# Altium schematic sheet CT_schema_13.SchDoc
size 385 x 385 mm
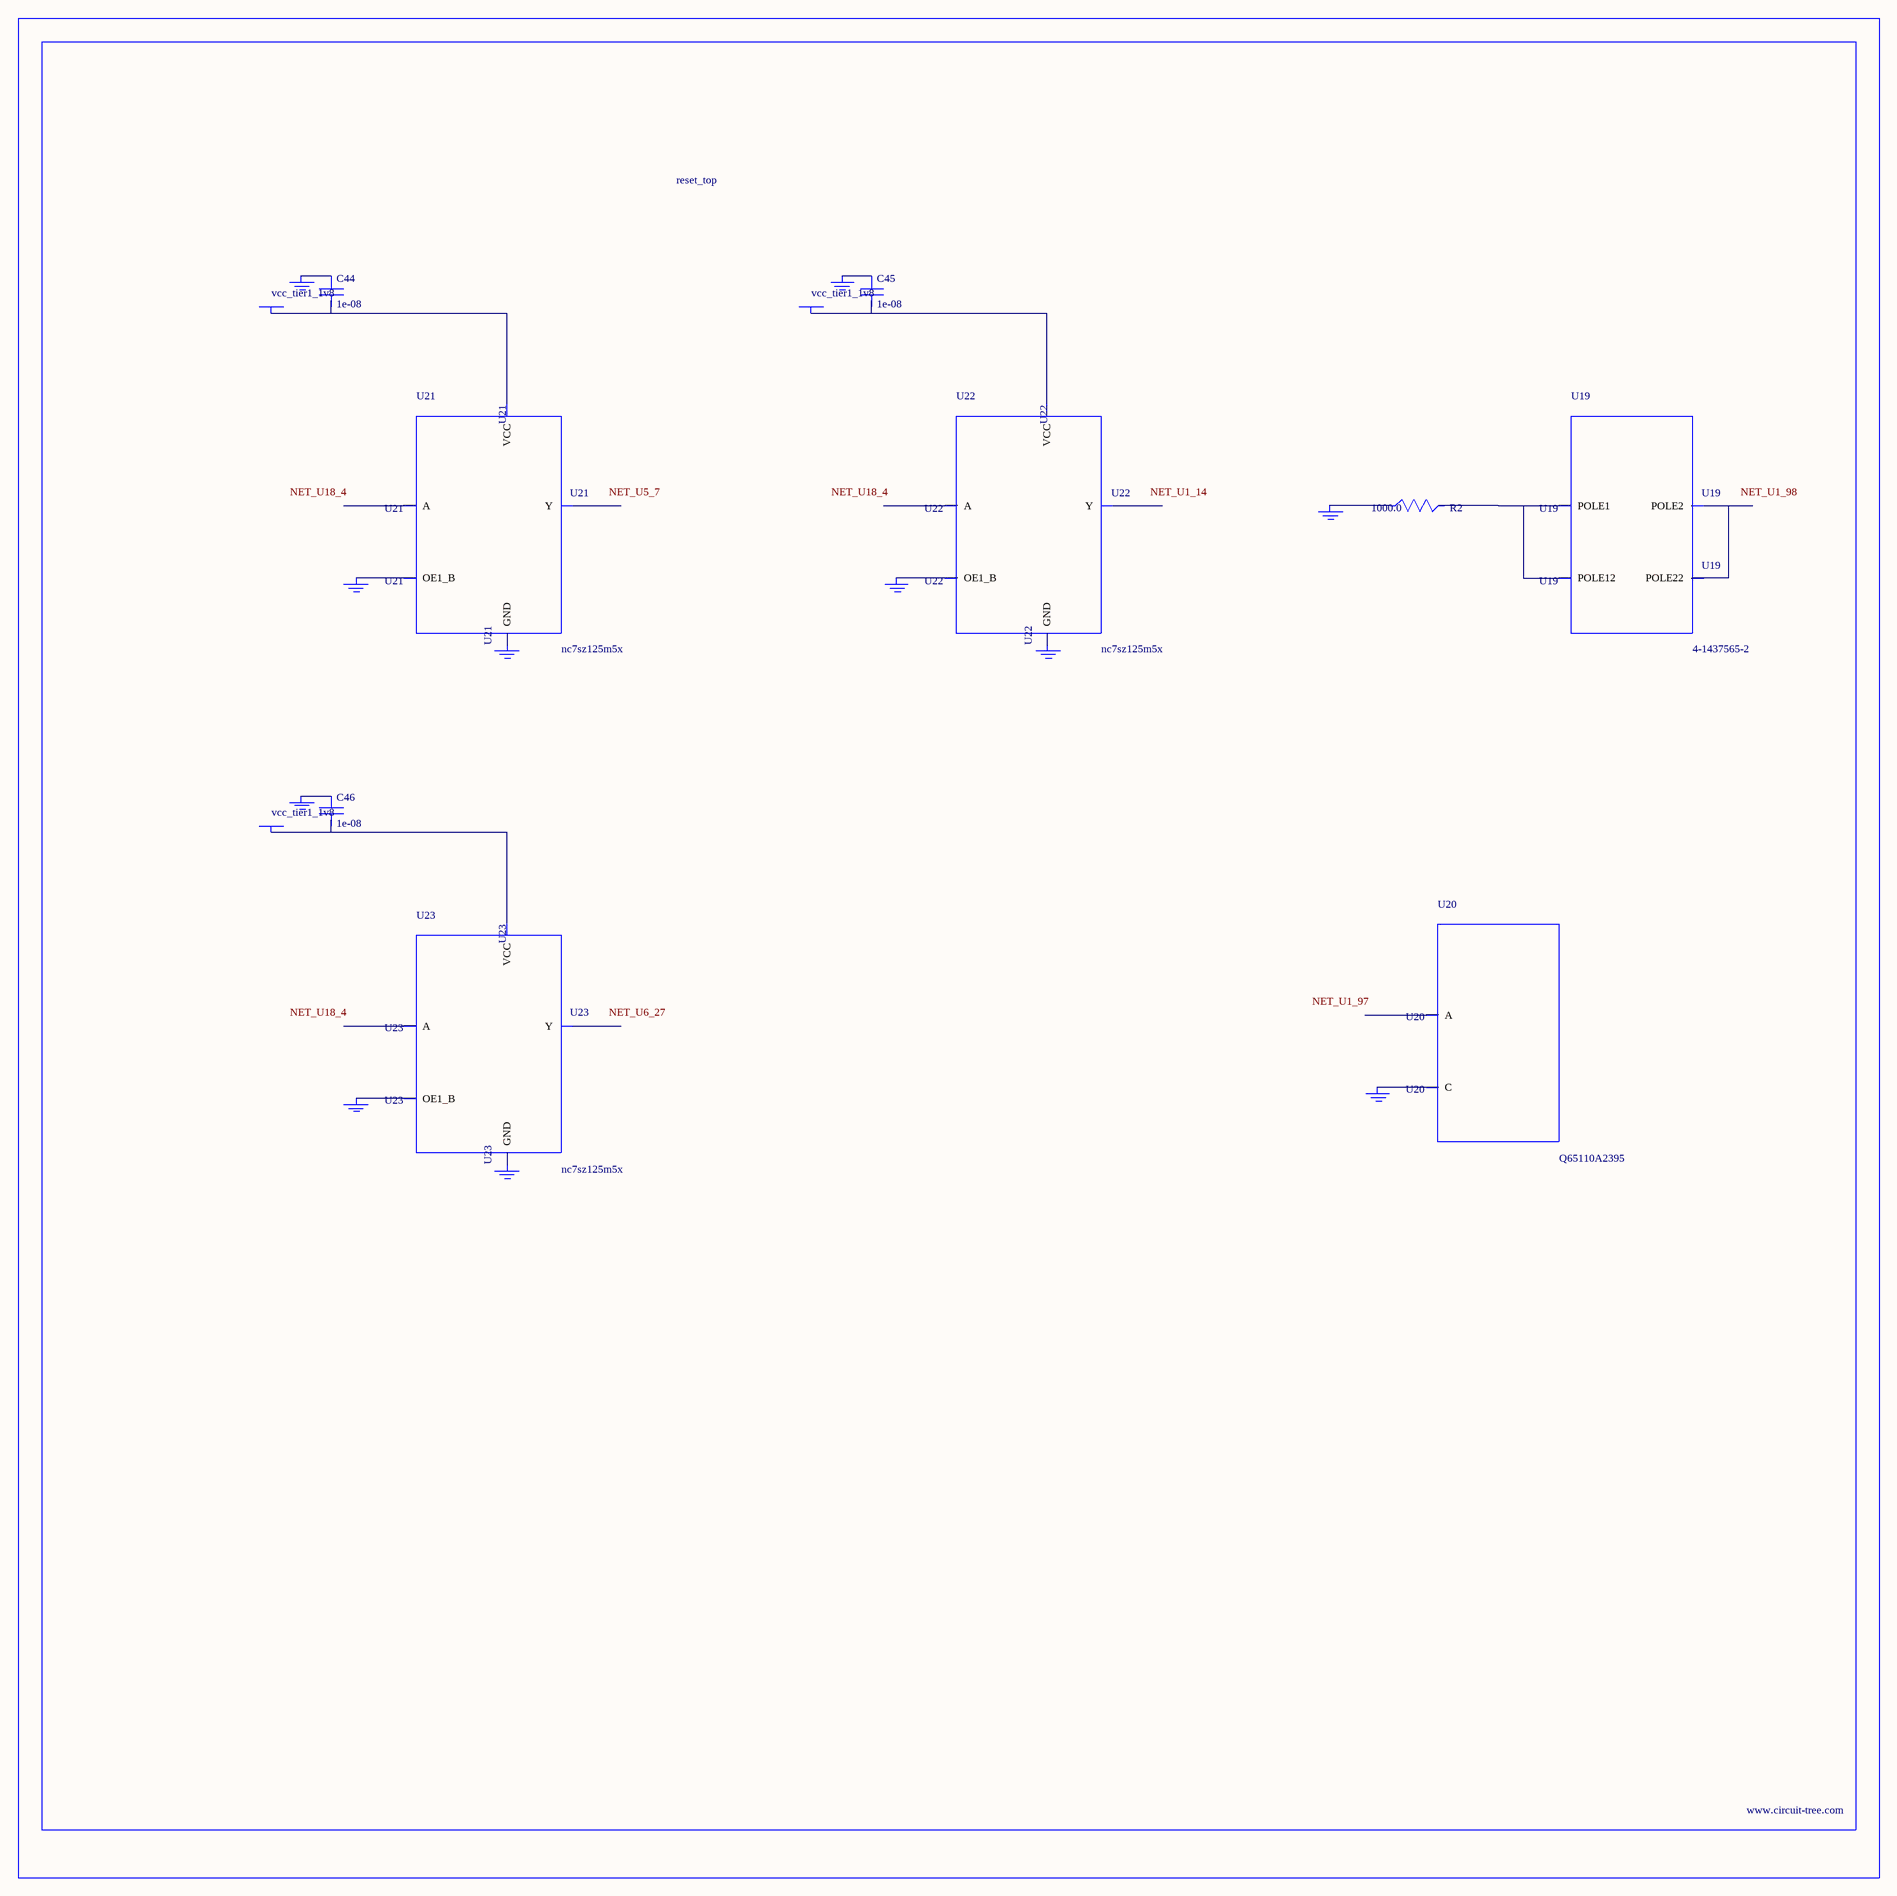
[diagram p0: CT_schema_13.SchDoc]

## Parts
BORDER12  (no value)
C44  1e-08  [C0402]
C45  1e-08  [C0402]
C46  1e-08  [C0402]
GND_INSTANCE_12_0  (no value)
GND_INSTANCE_12_1  (no value)
GND_INSTANCE_12_2  (no value)
GND_INSTANCE_12_3  (no value)
GND_INSTANCE_12_4  (no value)
GND_INSTANCE_12_5  (no value)
GND_INSTANCE_12_6  (no value)
GND_INSTANCE_12_7  (no value)
GND_INSTANCE_12_8  (no value)
GND_INSTANCE_12_9  (no value)
GND_INSTANCE_12_10  (no value)
POWER_INSTANCE_12_0  vcc_tier1_1v8
POWER_INSTANCE_12_1  vcc_tier1_1v8
POWER_INSTANCE_12_2  vcc_tier1_1v8
R2  1000.0  [R0603]
U19  4-1437565-2  [SW_4-1437565-2]
U20  Q65110A2395  [LGM67K-G1J2-24-Z]
U21  nc7sz125m5x  [NC7SZ125M5X]
U22  nc7sz125m5x  [NC7SZ125M5X]
U23  nc7sz125m5x  [NC7SZ125M5X]

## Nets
NetC44_1: C44.1 GND_INSTANCE_12_2.0(GND)
NetC44_2: C44.2 POWER_INSTANCE_12_0.0(PWR) U21.5(VCC)
NetC45_1: C45.1 GND_INSTANCE_12_5.0(GND)
NetC45_2: C45.2 POWER_INSTANCE_12_1.0(PWR) U22.5(VCC)
NetC46_1: C46.1 GND_INSTANCE_12_8.0(GND)
NetC46_2: C46.2 POWER_INSTANCE_12_2.0(PWR) U23.5(VCC)
NetGND_INSTANCE_12_0_0: GND_INSTANCE_12_0.0(GND) R2.1
NetGND_INSTANCE_12_1_0: GND_INSTANCE_12_1.0(GND) U20.C
NetGND_INSTANCE_12_3_0: GND_INSTANCE_12_3.0(GND) U21.1(OE1_B)
NetGND_INSTANCE_12_4_0: GND_INSTANCE_12_4.0(GND) U21.3(GND)
NetGND_INSTANCE_12_6_0: GND_INSTANCE_12_6.0(GND) U22.1(OE1_B)
NetGND_INSTANCE_12_7_0: GND_INSTANCE_12_7.0(GND) U22.3(GND)
NetGND_INSTANCE_12_9_0: GND_INSTANCE_12_9.0(GND) U23.1(OE1_B)
NetGND_INSTANCE_12_10_0: GND_INSTANCE_12_10.0(GND) U23.3(GND)
NetR2_2: R2.2 U19.1(POLE1) U19.2(POLE12)
NetU19_3: U19.3(POLE2) U19.4(POLE22)

Not connected (* = marked no-connect by the designer): U20 A; U21 2(A) 4(Y); U22 2(A) 4(Y); U23 2(A) 4(Y)

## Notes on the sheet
- Labels drawn without touching a wire or pin: NET_U1_14, NET_U1_97, NET_U1_98, NET_U5_7, NET_U6_27, NET_U18_4

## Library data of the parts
BORDER12 = BORDER_PAGE12
C44-C46 = C0402C103K3RAC
GND_INSTANCE_12_0-GND_INSTANCE_12_10 = GND
POWER_INSTANCE_12_0-POWER_INSTANCE_12_2 = PWR
R2 = RC0603JR-071KL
